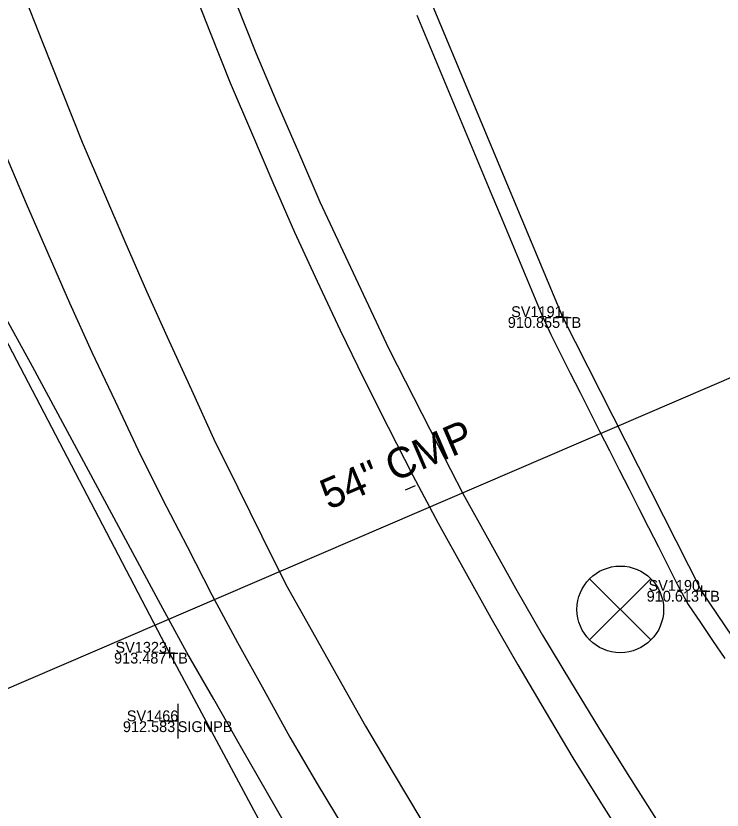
# Model space of a CAD drawing. Extents: x 1918148 to 1919797, y 624701 to 627089.
# Drawn here: x 1918934.8 to 1919000, y 625582 to 625655.4 of the extents above; entities that cross this region are included whole.
import ezdxf

# ---------------------------------------------------------------- set-up
doc = ezdxf.new("R2010")
doc.units = 0
for name, color, linetype in [('Default', 7, 'Continuous'), ('DR_X_Storm_Sewer', 7, 'Continuous'), ('DR_X_Text', 7, 'Continuous'), ('PM_X_Edge_Line', 7, 'Continuous'), ('PV_X_Shoulder_Aggregate', 7, 'Continuous'), ('RD_X_Concrete_Pad', 7, 'Continuous'), ('SN_X_Public', 7, 'Continuous'), ('SV_X_Shot_Marker', 7, 'Continuous'), ('SV_X_Text_Comment', 7, 'Continuous'), ('SV_X_Text_Elevation', 7, 'Continuous'), ('SV_X_Text_Name', 7, 'Continuous'), ('SV_X_Top_of_Bank', 7, 'Continuous')]:
    doc.layers.add(name, color=color, linetype=linetype)

msp = doc.modelspace()

# ---------------------------------------------------------------- linework, layer by layer
at = {"layer": 'Default'}
for p, q in [((1918987.752, 625603.386), (1918993.408, 625597.73)), ((1918987.752, 625597.73), (1918993.408, 625603.386)), ((1918990.58, 625600.558), (1918990.58, 625600.558))]:
    msp.add_line(p, q, dxfattribs=at)
msp.add_circle((1918990.58, 625600.558), 4, dxfattribs=at)
at = {"layer": 'DR_X_Storm_Sewer'}
msp.add_line((1918912.397, 625583.966), (1919031.605, 625635.224), dxfattribs=at)
at = {"layer": 'DR_X_Text'}
msp.add_line((1918971.624, 625611.958), (1918970.729, 625611.574), dxfattribs=at)
at = {"layer": 'PM_X_Edge_Line'}
for points in [[(1918933.638, 625662.357), (1918935.367, 625657.665), (1918937.202, 625653.014), (1918939.037, 625648.363), (1918940.884, 625643.717), (1918942.863, 625639.125), (1918944.843, 625634.533), (1918946.828, 625629.945), (1918948.901, 625625.395), (1918950.974, 625620.845), (1918953.053, 625616.297), (1918955.265, 625611.813), (1918957.478, 625607.33), (1918959.71, 625602.856), (1918962.154, 625598.494), (1918964.597, 625594.132), (1918967.049, 625589.774), (1918969.598, 625585.473), (1918972.148, 625581.172)], [(1918950.883, 625658.494), (1918952.719, 625653.844), (1918954.569, 625649.199), (1918956.526, 625644.598), (1918958.484, 625639.997), (1918960.482, 625635.414), (1918962.601, 625630.885), (1918964.72, 625626.356), (1918966.884, 625621.849), (1918969.154, 625617.394), (1918971.423, 625612.939), (1918973.759, 625608.519), (1918976.19, 625604.15), (1918978.621, 625599.781), (1918981.111, 625595.445), (1918983.657, 625591.142), (1918986.204, 625586.839), (1918988.839, 625582.591), (1918991.53, 625578.377)]]:
    msp.add_lwpolyline(points, dxfattribs=at)
at = {"layer": 'PV_X_Shoulder_Aggregate'}
for points in [[(1918971.778, 625655.448), (1918972.548, 625653.603), (1918973.318, 625651.757), (1918974.087, 625649.911), (1918974.857, 625648.066), (1918975.627, 625646.22), (1918976.396, 625644.375), (1918977.166, 625642.529), (1918977.935, 625640.684), (1918978.705, 625638.838), (1918979.475, 625636.992), (1918980.244, 625635.147), (1918981.014, 625633.301), (1918981.784, 625631.456), (1918982.553, 625629.61), (1918983.323, 625627.765), (1918984.159, 625625.95), (1918985.063, 625624.165), (1918985.966, 625622.381), (1918986.869, 625620.597), (1918987.773, 625618.813), (1918988.676, 625617.028), (1918989.579, 625615.244), (1918990.483, 625613.46), (1918991.386, 625611.675), (1918992.289, 625609.891), (1918993.193, 625608.107), (1918994.096, 625606.323), (1918994.999, 625604.538), (1918995.903, 625602.754), (1918996.859, 625601.001), (1918997.98, 625599.345), (1918999.101, 625597.688), (1919000.221, 625596.032)], [(1918960.494, 625579.243), (1918958.008, 625583.579), (1918955.522, 625587.915), (1918953.036, 625592.252), (1918950.55, 625596.588), (1918948.16, 625600.979), (1918945.786, 625605.379), (1918943.412, 625609.779), (1918941.037, 625614.179), (1918938.663, 625618.58), (1918936.289, 625622.98), (1918933.915, 625627.38)]]:
    msp.add_lwpolyline(points, dxfattribs=at)
at = {"layer": 'RD_X_Concrete_Pad'}
for points in [[(1918955.073, 625656.624), (1918956.925, 625651.98), (1918958.877, 625647.377), (1918960.855, 625642.785), (1918962.833, 625638.193), (1918964.954, 625633.665), (1918967.079, 625629.139), (1918969.209, 625624.616), (1918971.48, 625620.161), (1918973.752, 625615.707), (1918976.048, 625611.266), (1918978.48, 625606.897), (1918980.912, 625602.529), (1918983.39, 625598.187), (1918985.979, 625593.909), (1918988.569, 625589.632), (1918991.202, 625585.382), (1918993.895, 625581.169)], [(1918933.772, 625642.643), (1918935.727, 625638.042), (1918937.718, 625633.455), (1918939.708, 625628.869), (1918941.793, 625624.324), (1918943.921, 625619.8), (1918946.05, 625615.276), (1918948.278, 625610.801), (1918950.573, 625606.358), (1918952.867, 625601.916), (1918955.234, 625597.512), (1918957.651, 625593.135), (1918960.067, 625588.758), (1918962.586, 625584.44), (1918965.185, 625580.168)]]:
    msp.add_lwpolyline(points, dxfattribs=at)
at = {"layer": 'SN_X_Public'}
for p, q in [((1918949.713, 625591.822), (1918949.713, 625588.622)), ((1918949.713, 625590.222), (1918948.113, 625590.222))]:
    msp.add_line(p, q, dxfattribs=at)
at = {"layer": 'SV_X_Shot_Marker'}
for p, q in [((1918984.765, 625627.561), (1918985.765, 625627.561)), ((1918985.265, 625628.061), (1918985.265, 625627.061)), ((1918985.265, 625627.561), (1918985.265, 625627.561)), ((1918998.067, 625602.774), (1918998.067, 625601.774)), ((1918997.567, 625602.274), (1918998.567, 625602.274)), ((1918998.067, 625602.274), (1918998.067, 625602.274)), ((1918948.438, 625596.556), (1918949.438, 625596.556)), ((1918948.938, 625597.056), (1918948.938, 625596.056)), ((1918948.938, 625596.556), (1918948.938, 625596.556))]:
    msp.add_line(p, q, dxfattribs=at)
at = {"layer": 'SV_X_Top_of_Bank'}
for points in [[(1919180.035, 625377.767), (1919142.39, 625420.85), (1919113.902, 625458.171), (1919086.603, 625489.422), (1919057.387, 625523.08), (1919019.76, 625570.221), (1918998.067, 625602.274), (1918985.265, 625627.561), (1918968.388, 625668.032), (1918955.62, 625707.629), (1918947.904, 625739.173), (1918945.039, 625765.587), (1918947.372, 625785.939), (1918957.935, 625802.753), (1918975.613, 625809.208), (1918997.576, 625813.393), (1919030.667, 625814.442), (1919065.449, 625812.352), (1919111.287, 625808.541)], [(1919066.323, 625440.144), (1919029.777, 625482.468), (1919003.401, 625512.195), (1918983.316, 625538.257), (1918960.167, 625575.625), (1918948.938, 625596.556), (1918932.627, 625627.722), (1918922.22, 625652.786), (1918916.09, 625672.667), (1918901.238, 625716.643), (1918882.069, 625777.608)]]:
    msp.add_lwpolyline(points, dxfattribs=at)

# ---------------------------------------------------------------- texts
at = {"layer": 'DR_X_Text'}
msp.add_text('54" CMP', height=2.8, rotation=23.26712, dxfattribs=at).set_placement((1918963.649, 625609.728))
at = {"layer": 'SV_X_Text_Comment'}
for s, p in [('TB', (1918985.265, 625626.561)), ('TB', (1918998.067, 625601.274)), ('TB', (1918948.938, 625595.556)), ('SIGNPB', (1918949.713, 625589.222))]:
    msp.add_text(s, height=1, dxfattribs=at).set_placement(p)
at = {"layer": 'SV_X_Text_Elevation'}
for s, p in [('910.855', (1918980.194, 625626.561)), ('910.613', (1918993.017, 625601.274)), ('913.487', (1918943.835, 625595.556)), ('912.583', (1918944.649, 625589.222))]:
    msp.add_text(s, height=1, dxfattribs=at).set_placement(p)
at = {"layer": 'SV_X_Text_Name'}
for s, p in [('SV1191', (1918980.505, 625627.561)), ('SV1190', (1918993.187, 625602.274)), ('SV1323', (1918943.965, 625596.556)), ('SV1466', (1918945.011, 625590.222))]:
    msp.add_text(s, height=1, dxfattribs=at).set_placement(p)

doc.saveas('drawing.dxf')
